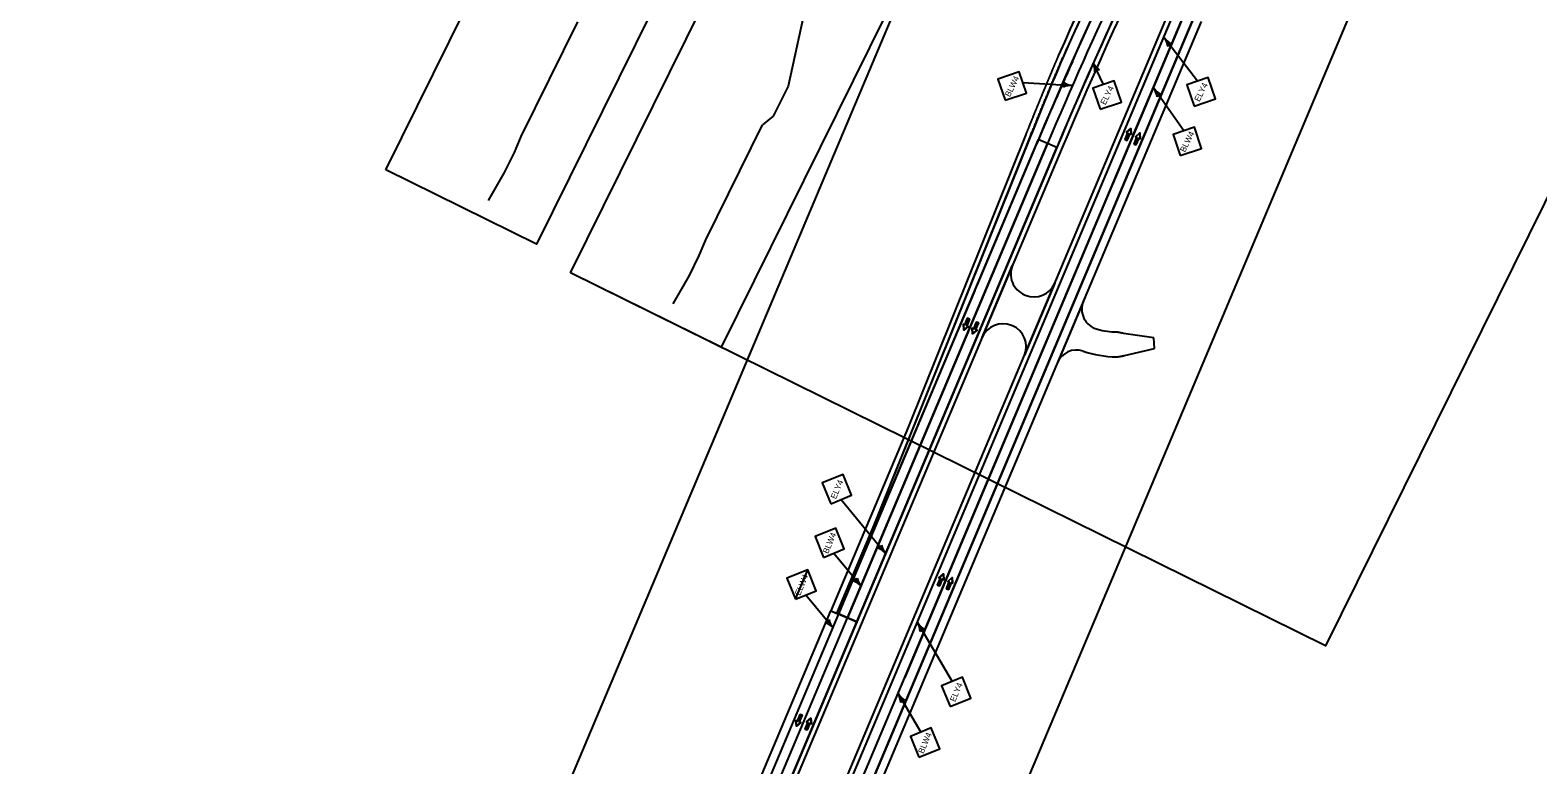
# Model space of a CAD drawing. Extents: x 14104283 to 14120882, y 8635219 to 8671666.
# Drawn here: x 14117444 to 14119252, y 8667263 to 8668145 of the extents above; entities that cross this region are included whole.
import ezdxf

# ---------------------------------------------------------------- set-up
doc = ezdxf.new("R2010")
doc.units = 0
for name, color, linetype in [('Cell', 7, 'Continuous'), ('dsnNonPlotable', 7, 'Continuous'), ('dsnPaintExistingEdgeLineRightWhite', 7, 'Continuous'), ('dsnPaintPlaceBrokenLineWhite', 7, 'Continuous'), ('dsnPaintPlaceEdgeLineLeftYellow', 7, 'Continuous'), ('dsnPaintPlaceEdgeLineRightWhite', 7, 'Continuous'), ('dsnPaintRemoveDoubleCenterLineYellow', 7, 'Continuous'), ('dsnShadingPaved', 7, 'Continuous'), ('dsnStdLabel', 7, 'Continuous'), ('dsnStgShadingPrevPav', 7, 'Continuous'), ('dsnTapePlaceEdgeLineLeftYellow', 7, 'Continuous'), ('dsnTextFinalPlan', 7, 'Continuous'), ('dsnTextOverlapEven', 7, 'Continuous'), ('Level 2', 7, 'Continuous'), ('Level 5', 7, 'Continuous'), ('Terrain', 7, 'Continuous')]:
    doc.layers.add(name, color=color, linetype=linetype)

msp = doc.modelspace()

# ---------------------------------------------------------------- linework, layer by layer
at = {"layer": 'Cell'}
for points in [[(14118534.5, 8667478.1), (14118532.2, 8667479), (14118535.5, 8667487.1), (14118533.8, 8667487.8), (14118539.1, 8667492.4), (14118539.6, 8667485.4), (14118537.8, 8667486.2)], [(14118545.2, 8667473.7), (14118542.9, 8667474.6), (14118546.2, 8667482.7), (14118544.5, 8667483.4), (14118549.7, 8667488), (14118550.2, 8667481.1), (14118548.5, 8667481.8)], [(14118367.3, 8667323.8), (14118369.6, 8667322.9), (14118366.3, 8667314.8), (14118368, 8667314.1), (14118362.8, 8667309.5), (14118362.2, 8667316.5), (14118364, 8667315.7)], [(14118375.7, 8667305), (14118373.4, 8667305.9), (14118376.7, 8667314), (14118375, 8667314.7), (14118380.3, 8667319.3), (14118380.8, 8667312.3), (14118379, 8667313.1)]]:
    msp.add_lwpolyline(points, close=True, dxfattribs=at)
for points in [[(14118537.8, 8667486.2), (14118539.6, 8667485.4), (14118539.1, 8667492.4), (14118533.8, 8667487.8), (14118535.5, 8667487.1), (14118532.2, 8667479), (14118534.5, 8667478.1), (14118537.8, 8667486.2)], [(14118548.5, 8667481.8), (14118550.2, 8667481.1), (14118549.7, 8667488), (14118544.5, 8667483.4), (14118546.2, 8667482.7), (14118542.9, 8667474.6), (14118545.2, 8667473.7), (14118548.5, 8667481.8)], [(14118364, 8667315.7), (14118362.2, 8667316.5), (14118362.8, 8667309.5), (14118368, 8667314.1), (14118366.3, 8667314.8), (14118369.6, 8667322.9), (14118367.3, 8667323.8), (14118364, 8667315.7)], [(14118379, 8667313.1), (14118380.8, 8667312.3), (14118380.3, 8667319.3), (14118375, 8667314.7), (14118376.7, 8667314), (14118373.4, 8667305.9), (14118375.7, 8667305), (14118379, 8667313.1)]]:
    msp.add_lwpolyline(points, dxfattribs=at)
at = {"layer": 'dsnNonPlotable'}
for points in [[(14118092, 8667853.7), (14118786.8, 8669258.8), (14119692.1, 8668811.2), (14118997.4, 8667406.1)], [(14118056.5, 8667161.9), (14118665.1, 8668606.4), (14119130.4, 8668410.4), (14118521.9, 8666965.8)]]:
    msp.add_lwpolyline(points, close=True, dxfattribs=at)
at = {"layer": 'dsnPaintExistingEdgeLineRightWhite'}
msp.add_line((14110924.4, 8649364.5), (14118862.5, 8668214.7), dxfattribs=at)
at = {"layer": 'dsnPaintPlaceBrokenLineWhite'}
for p, q in [((14114932.5, 8658913.4), (14118951.7, 8668457.6)), ((14118664.1, 8668009), (14118424.3, 8667439.6)), ((14110829.5, 8649404.5), (14118424.3, 8667439.6))]:
    msp.add_line(p, q, dxfattribs=at)
msp.add_arc((14123733, 8665874.4), 5500, 152.6921, 157.1633, dxfattribs=at)
at = {"layer": 'dsnPaintPlaceEdgeLineLeftYellow'}
for p, q in [((14115900.9, 8661244), (14118817.4, 8668169.6)), ((14118675.1, 8668004.3), (14118435.4, 8667434.9)), ((14118435.4, 8667434.9), (14115816.1, 8661215.2))]:
    msp.add_line(p, q, dxfattribs=at)
at = {"layer": 'dsnPaintPlaceEdgeLineRightWhite'}
for p, q in [((14118643.5, 8668017.6), (14118412.9, 8667444.4)), ((14118413.2, 8667444.3), (14115798.8, 8661235.7))]:
    msp.add_line(p, q, dxfattribs=at)
for centre, radius, start, end in [((14123733, 8665874.4), 5524, 150.3689, 156.0986), ((14123767.9, 8665959.1), 5522.4, 157.0492, 158.1143)]:
    msp.add_arc(centre, radius, start, end, dxfattribs=at)
at = {"layer": 'dsnPaintRemoveDoubleCenterLineYellow'}
for p in [(14118767, 8668018.9), (14114932.5, 8658913.4)]:
    msp.add_line(p, (14118493, 8667368.2), dxfattribs=at)
msp.add_lwpolyline([(14118767, 8668018.9), (14118845.6, 8668205.5), (14118851.5, 8668219.5)], dxfattribs=at)
at = {"layer": 'dsnShadingPaved'}
for p, q in [((14118227.7, 8666769.2), (14118940.7, 8668462.2)), ((14118962.8, 8668452.9), (14118249.8, 8666759.9)), ((14118693.6, 8668107.6), (14118694.1, 8668107.5)), ((14118528.4, 8667730.9), (14118643.5, 8668017.6)), ((14118675.1, 8668004.3), (14118653, 8668013.6)), ((14118646.5, 8667998.1), (14118579.3, 8667838.5)), ((14118576.7, 8667832.4), (14118534.2, 8667731.7)), ((14118534.2, 8667731.7), (14118412.9, 8667443.5)), ((14118412.9, 8667443.5), (14118528.4, 8667730.9)), ((14118435.4, 8667434.9), (14118413.2, 8667444.3))]:
    msp.add_line(p, q, dxfattribs=at)
for points in [[(14118653, 8668013.6), (14118412.9, 8667444.4), (14118424.3, 8667439.6), (14118664.1, 8668009)], [(14118435.4, 8667434.9), (14118675.1, 8668004.3), (14118664.1, 8668009), (14118424.2, 8667439.7)]]:
    msp.add_lwpolyline(points, close=True, dxfattribs=at)
for points in [[(14118413.2, 8667444.3), (14110818.4, 8649409.2), (14109142.6, 8645431.4)], [(14109164.7, 8645422.1), (14110840.5, 8649399.8), (14118435.4, 8667434.9)]]:
    msp.add_lwpolyline(points, dxfattribs=at)
for centre, radius, start, end in [((14123733, 8665874.4), 5512, 149.6777, 156.0986), ((14123733, 8665874.4), 5488, 152.6921, 157.1633), ((14123733, 8665874.4), 5512, 153.1692, 157.1633), ((14123733, 8665874.4), 5524, 153.2337, 156.0986), ((14123767.9, 8665959.1), 5522.4, 157.0492, 158.1143), ((14123265.6, 8666052.9), 5012, 155.8003, 157.1633)]:
    msp.add_arc(centre, radius, start, end, dxfattribs=at)
at = {"layer": 'dsnStdLabel'}
for p, q in [((14118951.7, 8668457.6), (14118742.2, 8667959.9)), ((14118844, 8668083.7), (14118804.3, 8668135.5)), ((14118731.3, 8668079.9), (14118718.8, 8668105.9)), ((14118634.4, 8668082.2), (14118694, 8668078.7)), ((14118827.4, 8668024.3), (14118791.6, 8668075.2)), ((14118416.6, 8667581.6), (14118469.9, 8667517)), ((14118407.8, 8667517.3), (14118440.8, 8667477.3)), ((14118361.7, 8667462), (14118376.5, 8667497.2)), ((14118374.2, 8667467.1), (14118406.8, 8667427.6)), ((14118508.2, 8667433.9), (14118549.5, 8667363.2)), ((14118484.9, 8667348.7), (14118512, 8667302.3))]:
    msp.add_line(p, q, dxfattribs=at)
for points in [[(14118613.1, 8668060.8), (14118638.7, 8668069.4), (14118630, 8668095), (14118604.4, 8668086.3)], [(14118727.2, 8668050), (14118752.7, 8668058.6), (14118744.1, 8668084.2), (14118718.5, 8668075.5)], [(14118839.9, 8668053.8), (14118865.4, 8668062.4), (14118856.8, 8668088), (14118831.2, 8668079.4)], [(14118823.3, 8667994.4), (14118848.8, 8668003), (14118840.2, 8668028.6), (14118814.6, 8668019.9)], [(14118404.1, 8667576.5), (14118429.1, 8667586.7), (14118418.9, 8667611.7), (14118393.9, 8667601.5)], [(14118395.3, 8667512.2), (14118420.3, 8667522.3), (14118410.2, 8667547.4), (14118385.2, 8667537.2)], [(14118361.7, 8667462), (14118386.7, 8667472.2), (14118376.5, 8667497.2), (14118351.5, 8667487.1)], [(14118547.2, 8667333.1), (14118572.2, 8667343.3), (14118562, 8667368.3), (14118537, 8667358.1)], [(14118509.7, 8667272.2), (14118534.7, 8667282.4), (14118524.5, 8667307.4), (14118499.5, 8667297.2)]]:
    msp.add_lwpolyline(points, close=True, dxfattribs=at)
for centre, radius, start, end in [((14118786.1, 8668121.5), 22.9, 9.4145, 37.4858), ((14118822.5, 8668149.4), 22.9, 217.4856, 245.5569), ((14118816, 8668120.2), 8.86, 109.7515, 145.2199), ((14118698.1, 8668096), 22.9, 357.4572, 25.5285), ((14118739.6, 8668115.8), 22.9, 205.5284, 233.5996), ((14118674.8, 8668079.9), 8.86, 338.925, 14.3935), ((14118695.4, 8668101.6), 22.9, 238.5881, 266.6594), ((14118727.1, 8668088.6), 8.86, 97.7942, 133.2627), ((14118692.7, 8668055.8), 22.9, 86.6592, 114.7305), ((14118772.8, 8668062), 22.9, 7.0336, 35.1049), ((14118810.4, 8668088.4), 22.9, 215.1048, 243.176), ((14118802.6, 8668059.5), 8.86, 107.3706, 142.8391), ((14118457.4, 8667531.6), 8.86, 292.8385, 328.307), ((14118452.5, 8667502.1), 22.9, 40.5727, 68.6439), ((14118487.4, 8667531.9), 22.9, 192.5015, 220.5728), ((14118428.3, 8667491.9), 8.86, 292.8385, 328.307), ((14118423.4, 8667462.4), 22.9, 40.5727, 68.6439), ((14118458.2, 8667492.2), 22.9, 192.5015, 220.5728), ((14118394.3, 8667442.2), 8.86, 292.8385, 328.307), ((14118389.4, 8667412.6), 22.9, 40.5727, 68.6439), ((14118424.3, 8667442.5), 22.9, 192.5015, 220.5728), ((14118488.4, 8667422.4), 22.9, 2.1566, 30.2279), ((14118528, 8667445.5), 22.9, 210.2277, 238.299), ((14118517.9, 8667417.3), 8.86, 102.4935, 137.962), ((14118465.1, 8667337.2), 22.9, 2.1566, 30.2279), ((14118504.7, 8667360.3), 22.9, 210.2277, 238.299), ((14118494.6, 8667332.1), 8.86, 102.4935, 137.962)]:
    msp.add_arc(centre, radius, start, end, dxfattribs=at)
at = {"layer": 'dsnStgShadingPrevPav'}
for p, q in [((14115895.6, 8661246.8), (14118811.5, 8668171)), ((14118848.4, 8668155.5), (14115932.5, 8661231.3)), ((14118653, 8668013.6), (14115794, 8661224.5)), ((14118652.6, 8668013.1), (14118415.9, 8667450.9)), ((14118458, 8667555.6), (14118643.5, 8668017.6)), ((14118458, 8667555.6), (14118643.5, 8668017.6)), ((14118638, 8668019.9), (14118497.2, 8667669.3)), ((14115816.1, 8661215.2), (14118675.1, 8668004.3)), ((14115816.1, 8661215.2), (14118675.1, 8668004.3)), ((14118680.7, 8668002), (14115821.7, 8661212.9)), ((14118585.6, 8667776.2), (14118622.1, 8667862.8)), ((14118672.7, 8667841.4), (14118636.3, 8667754.8)), ((14118636.5, 8667827.4), (14118637.4, 8667827)), ((14118707.1, 8667819.9), (14118675.9, 8667745.8)), ((14118621.9, 8667790.2), (14118620.9, 8667790.6)), ((14118791.6, 8667775.6), (14118755.1, 8667781)), ((14118792.2, 8667763.1), (14118791.6, 8667775.6)), ((14118756.4, 8667754.5), (14118792.2, 8667763.1)), ((14118497.2, 8667669.3), (14118404, 8667448.1)), ((14118411.4, 8667445), (14118458, 8667555.6)), ((14118411.4, 8667445), (14118458, 8667555.6)), ((14110809.2, 8649413), (14118404, 8667448.1)), ((14118404, 8667448.1), (14118411.4, 8667445)), ((14118404, 8667448.1), (14118413.2, 8667444.3)), ((14118415.9, 8667450.9), (14118413.1, 8667444.3)), ((14118413.2, 8667444.3), (14110818.4, 8649409.2)), ((14118413.2, 8667444.3), (14118411.4, 8667445))]:
    msp.add_line(p, q, dxfattribs=at)
for centre, radius, start, end in [((14123733, 8665874.4), 5512, 146.4256, 157.1633), ((14123733, 8665874.4), 5488, 146.4212, 157.1633), ((14123733, 8665874.4), 5530, 150.3689, 156.0991), ((14123733, 8665874.4), 5524, 150.3689, 156.0986), ((14123733, 8665874.4), 5524, 150.3689, 156.0986), ((14123732.6, 8665873.8), 5512, 150.362, 157.1633), ((14123733, 8665874.4), 5482, 150.671, 157.1633), ((14123733, 8665874.4), 5488, 151.143, 157.1633), ((14118646.9, 8667852.3), 27, 157.1633, 247.1633), ((14118647.9, 8667851.9), 27, 247.1633, 337.1633), ((14118730.1, 8667810.2), 25, 157.1633, 255.6089), ((14118610.5, 8667765.7), 27, 67.1633, 157.1633), ((14118611.4, 8667765.3), 27, 337.1633, 67.1633), ((14118750, 8667887.7), 105, 255.6089, 268.5297), ((14118698.9, 8667736.1), 25, 71.3746, 157.1633), ((14118750, 8667887.7), 135, 251.3746, 268.5297)]:
    msp.add_arc(centre, radius, start, end, dxfattribs=at)
for points, degree in [([(14118677.1, 8668114.8), (14118676.8, 8668113.9), (14118675.5, 8668110.8), (14118673.1, 8668105.2), (14118671.2, 8668100.7), (14118669.2, 8668095.9), (14118667.2, 8668091.2), (14118665.2, 8668086.4), (14118663.2, 8668081.7), (14118661.3, 8668076.9), (14118659.3, 8668072.2), (14118657.3, 8668067.4), (14118655.4, 8668062.7), (14118653.4, 8668057.9), (14118651.5, 8668053.2), (14118649.5, 8668048.4), (14118647.6, 8668043.7), (14118645.7, 8668038.9), (14118643.7, 8668034.1), (14118641.9, 8668029.6), (14118639.6, 8668023.9), (14118638.3, 8668020.8), (14118638, 8668019.9)], 2), ([(14118643.5, 8668017.6), (14118644.2, 8668019.2), (14118645.4, 8668022.4), (14118647.4, 8668027.1), (14118649.3, 8668031.9), (14118651.2, 8668036.6), (14118653.1, 8668041.4), (14118655.1, 8668046.2), (14118657, 8668050.9), (14118659, 8668055.7), (14118660.9, 8668060.4), (14118662.9, 8668065.1), (14118664.8, 8668069.9), (14118666.8, 8668074.6), (14118668.8, 8668079.4), (14118670.7, 8668084.1), (14118672.7, 8668088.8), (14118674.7, 8668093.6), (14118676.7, 8668098.3), (14118678.7, 8668103), (14118680.7, 8668107.8), (14118682, 8668110.9), (14118682.7, 8668112.5)], 3), ([(14118643.5, 8668017.6), (14118644.2, 8668019.2), (14118645.4, 8668022.4), (14118647.4, 8668027.1), (14118649.3, 8668031.9), (14118651.2, 8668036.6), (14118653.1, 8668041.4), (14118655.1, 8668046.2), (14118657, 8668050.9), (14118659, 8668055.7), (14118660.9, 8668060.4), (14118662.9, 8668065.1), (14118664.8, 8668069.9), (14118666.8, 8668074.6), (14118668.8, 8668079.4), (14118670.7, 8668084.1), (14118672.7, 8668088.8), (14118674.7, 8668093.6), (14118676.7, 8668098.3), (14118678.7, 8668103), (14118680.7, 8668107.8), (14118682, 8668110.9), (14118682.7, 8668112.5)], 3), ([(14118755.1, 8667781), (14118755, 8667781.1), (14118754.7, 8667781.1), (14118754.3, 8667781.2), (14118754, 8667781.2), (14118753.6, 8667781.3), (14118753.2, 8667781.4), (14118752.8, 8667781.5), (14118752.4, 8667781.6), (14118752, 8667781.6), (14118751.6, 8667781.7), (14118751.2, 8667781.8), (14118750.8, 8667781.9), (14118750.4, 8667782), (14118750, 8667782.1), (14118749.6, 8667782.2), (14118749.2, 8667782.2), (14118748.8, 8667782.3), (14118748.5, 8667782.4), (14118748.1, 8667782.5), (14118747.7, 8667782.6), (14118747.4, 8667782.7), (14118747.3, 8667782.7)], 3), ([(14118746.5, 8667752.7), (14118746.7, 8667752.8), (14118747, 8667752.8), (14118747.5, 8667752.9), (14118748, 8667752.9), (14118748.5, 8667753), (14118749, 8667753.1), (14118749.5, 8667753.2), (14118750, 8667753.3), (14118750.5, 8667753.4), (14118751, 8667753.4), (14118751.5, 8667753.5), (14118752, 8667753.6), (14118752.5, 8667753.7), (14118753, 8667753.8), (14118753.5, 8667753.9), (14118754, 8667754), (14118754.5, 8667754.1), (14118755, 8667754.2), (14118755.4, 8667754.3), (14118755.9, 8667754.4), (14118756.3, 8667754.5), (14118756.4, 8667754.5)], 3)]:
    msp.add_open_spline(points, degree=degree, dxfattribs=at)
at = {"layer": 'dsnTapePlaceEdgeLineLeftYellow'}
msp.add_arc((14123733, 8665874.4), 5488, 152.6921, 157.1633, dxfattribs=at)
at = {"layer": 'dsnTextFinalPlan'}
for points in [[(14117870.4, 8667977.4), (14118384.9, 8669018.2), (14118565.6, 8668928.9), (14118051, 8667888.1)], [(14118092, 8667853.7), (14118606.6, 8668894.4), (14118787.2, 8668805.1), (14118272.7, 8667764.4)]]:
    msp.add_lwpolyline(points, close=True, dxfattribs=at)
at = {"layer": 'dsnTextOverlapEven'}
msp.add_lwpolyline([(14117870.4, 8667977.4), (14118384.9, 8669018.2), (14118565.6, 8668928.9), (14118051, 8667888.1)], close=True, dxfattribs=at)
at = {"layer": 'Level 2'}
for points in [[(14118757.1, 8668013.6), (14118759.4, 8668012.7), (14118762.8, 8668020.7), (14118764.5, 8668020), (14118764.1, 8668027), (14118758.8, 8668022.4), (14118760.5, 8668021.7)], [(14118767.9, 8668008.3), (14118770.2, 8668007.4), (14118773.6, 8668015.4), (14118775.3, 8668014.7), (14118774.8, 8668021.7), (14118769.5, 8668017.1), (14118771.3, 8668016.4)], [(14118570.5, 8667798.3), (14118568.2, 8667799.3), (14118564.8, 8667791.2), (14118563.1, 8667792), (14118563.6, 8667785), (14118568.9, 8667789.5), (14118567.1, 8667790.3)], [(14118581.2, 8667793.8), (14118578.9, 8667794.7), (14118575.5, 8667786.7), (14118573.7, 8667787.4), (14118574.2, 8667780.4), (14118579.5, 8667785), (14118577.8, 8667785.7)]]:
    msp.add_lwpolyline(points, close=True, dxfattribs=at)
at = {"layer": 'Level 5'}
for points in [[(14118760.5, 8668021.7), (14118758.8, 8668022.4), (14118764.1, 8668027), (14118764.5, 8668020), (14118762.8, 8668020.7), (14118759.4, 8668012.7), (14118757.1, 8668013.6), (14118760.5, 8668021.7)], [(14118771.3, 8668016.4), (14118769.5, 8668017.1), (14118774.8, 8668021.7), (14118775.3, 8668014.7), (14118773.6, 8668015.4), (14118770.2, 8668007.4), (14118767.9, 8668008.3), (14118771.3, 8668016.4)], [(14118567.1, 8667790.3), (14118568.9, 8667789.5), (14118563.6, 8667785), (14118563.1, 8667792), (14118564.8, 8667791.2), (14118568.2, 8667799.3), (14118570.5, 8667798.3), (14118567.1, 8667790.3)], [(14118577.8, 8667785.7), (14118579.5, 8667785), (14118574.2, 8667780.4), (14118573.7, 8667787.4), (14118575.5, 8667786.7), (14118578.9, 8667794.7), (14118581.2, 8667793.8), (14118577.8, 8667785.7)]]:
    msp.add_lwpolyline(points, dxfattribs=at)
at = {"layer": 'Terrain'}
for p, q in [((14118377.1, 8668189.1), (14118352.8, 8668077.6)), ((14118032.5, 8668017.2), (14118100.5, 8668154.9)), ((14118352.8, 8668077.6), (14118335, 8668041.8)), ((14118254.1, 8667893.5), (14118322.2, 8668031.2)), ((14118335, 8668041.8), (14118322.2, 8668031.2))]:
    msp.add_line(p, q, dxfattribs=at)
for points in [[(14117993.4, 8667940.4), (14118012.8, 8667974.2), (14118024.6, 8667998.1), (14118032.5, 8668017.2)], [(14118215.1, 8667816.7), (14118234.5, 8667850.5), (14118246.3, 8667874.4), (14118254.1, 8667893.5)]]:
    msp.add_lwpolyline(points, dxfattribs=at)

# ---------------------------------------------------------------- texts
at = {"layer": 'dsnStdLabel'}
for s, rotation, p in [('BLW4', 63.6912, (14118618.8, 8668064.2)), ('ELY4', 63.6912, (14118846.2, 8668058.5)), ('ELY4', 63.6912, (14118733.5, 8668054.7)), ('BLW4', 63.6912, (14118829, 8667997.8)), ('ELY4', 67.1547, (14118410.2, 8667581.6)), ('BLW4', 67.1547, (14118400.8, 8667516)), ('ELW4', 67.1547, (14118367.2, 8667465.8)), ('ELY4', 67.1547, (14118553.3, 8667338.2)), ('BLW4', 67.1547, (14118515.2, 8667276))]:
    msp.add_text(s, height=7.2, rotation=rotation, dxfattribs=at).set_placement(p)

doc.saveas('drawing.dxf')
